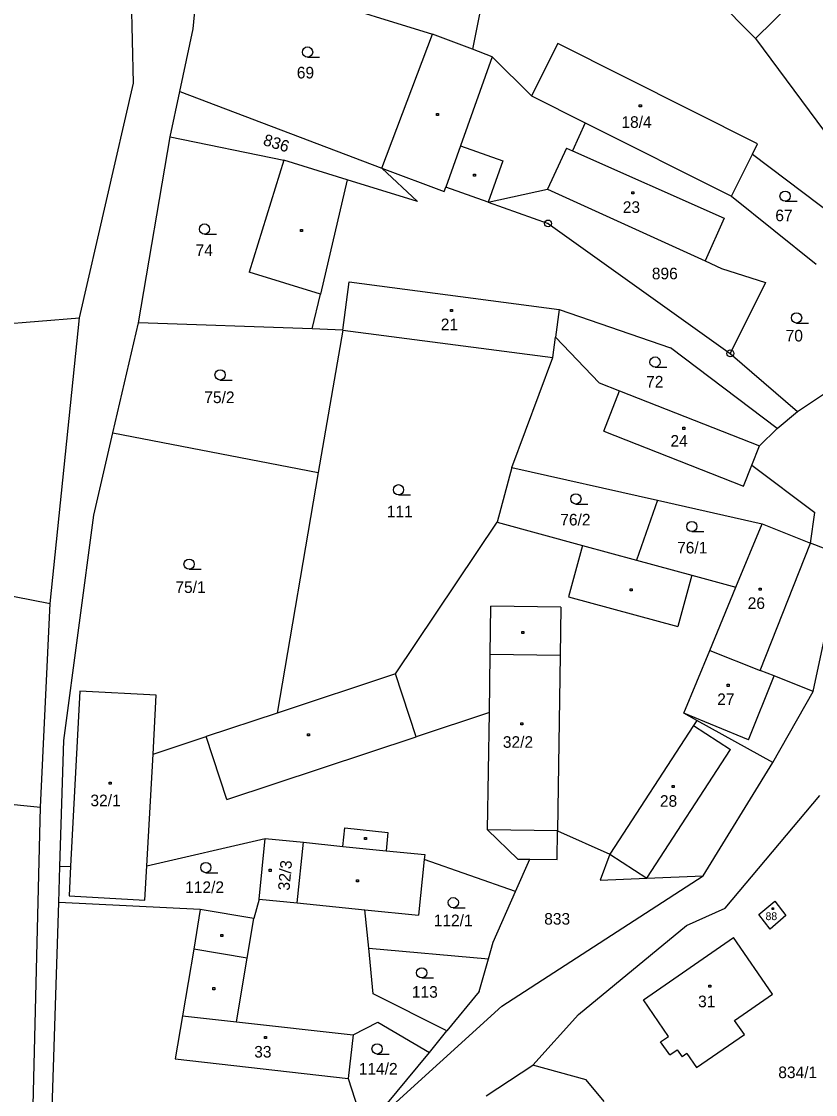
# Model space of a CAD drawing. Extents: x -791032 to -787751, y -1106872 to -1104403.
# Drawn here: x -789576 to -789459.7, y -1105520.6 to -1105363.5 of the extents above; entities that cross this region are included whole.
import ezdxf

# ---------------------------------------------------------------- set-up
doc = ezdxf.new("R2010")
doc.units = 0
for name, color, linetype in [('Vrstva 1', 7, 'Continuous'), ('Vrstva 14', 7, 'Continuous'), ('Vrstva 15', 7, 'Continuous'), ('Vrstva 2', 7, 'Continuous'), ('Vrstva 23', 7, 'Continuous'), ('Vrstva 25', 7, 'Continuous'), ('Vrstva 28', 7, 'Continuous')]:
    doc.layers.add(name, color=color, linetype=linetype)

msp = doc.modelspace()

# ---------------------------------------------------------------- linework, layer by layer
at = {"layer": 'Vrstva 1'}
for p, q in [((-789468.52, -1105366.04), (-789491.02, -1105343.38)), ((-789550.83, -1105364.62), (-789549.93, -1105354.86)), ((-789549.93, -1105354.86), (-789515.79, -1105365.39)), ((-789559.57, -1105372.57), (-789559.95, -1105356.13)), ((-789508.16, -1105358.69), (-789509.94, -1105367.61)), ((-789468.52, -1105366.04), (-789463.32, -1105360.91)), ((-789552.79, -1105373.8), (-789550.83, -1105364.62)), ((-789523.22, -1105385), (-789515.79, -1105365.39)), ((-789509.94, -1105367.61), (-789515.79, -1105365.39)), ((-789497.46, -1105366.76), (-789501.32, -1105374.44)), ((-789468.22, -1105381.48), (-789497.46, -1105366.76)), ((-789468.52, -1105366.04), (-789452.74, -1105387.39)), ((-789507.08, -1105368.73), (-789509.94, -1105367.61)), ((-789507.08, -1105368.73), (-789501.32, -1105374.44)), ((-789567.47, -1105406.94), (-789559.57, -1105372.57)), ((-789554.21, -1105380.44), (-789552.79, -1105373.8)), ((-789552.79, -1105373.8), (-789523.22, -1105385)), ((-789501.32, -1105374.44), (-789493.46, -1105378.39)), ((-789493.46, -1105378.39), (-789495.3, -1105382.5)), ((-789493.46, -1105378.39), (-789472.06, -1105389.13)), ((-789558.84, -1105407.68), (-789554.21, -1105380.44)), ((-789554.21, -1105380.44), (-789537.56, -1105383.85)), ((-789468.96, -1105382.96), (-789468.22, -1105381.48)), ((-789495.3, -1105382.5), (-789473.12, -1105392.36)), ((-789472.06, -1105389.13), (-789468.96, -1105382.96)), ((-789468.96, -1105382.96), (-789456.6, -1105392.29)), ((-789537.56, -1105383.85), (-789542.63, -1105400.22)), ((-789528.28, -1105386.72), (-789537.56, -1105383.85)), ((-789523.22, -1105385), (-789514.09, -1105388.46)), ((-789523.22, -1105385), (-789517.97, -1105389.92)), ((-789517.97, -1105389.92), (-789528.28, -1105386.72)), ((-789514.09, -1105388.46), (-789513.85, -1105387.78)), ((-789507.64, -1105389.99), (-789513.85, -1105387.78)), ((-789507.64, -1105389.99), (-789498.95, -1105388.1)), ((-789498.95, -1105388.1), (-789475.9, -1105398.6)), ((-789472.06, -1105389.13), (-789459.64, -1105399.07)), ((-789507.64, -1105389.99), (-789498.89, -1105393.11)), ((-789473.12, -1105392.36), (-789475.9, -1105398.6)), ((-789498.89, -1105393.11), (-789472.21, -1105412.13)), ((-789475.9, -1105398.6), (-789473.49, -1105399.7)), ((-789532.2, -1105403.45), (-789542.63, -1105400.22)), ((-789473.49, -1105399.7), (-789467.07, -1105401.75)), ((-789467.07, -1105401.75), (-789472.21, -1105412.13)), ((-789533.4, -1105408.56), (-789532.2, -1105403.45)), ((-789497.27, -1105405.7), (-789497.8, -1105409.76)), ((-789497.27, -1105405.7), (-789480.95, -1105411.34)), ((-789634.19, -1105412.22), (-789567.47, -1105406.94)), ((-789571.77, -1105448.75), (-789567.47, -1105406.94)), ((-789562.57, -1105423.75), (-789558.84, -1105407.68)), ((-789533.4, -1105408.56), (-789558.84, -1105407.68)), ((-789528.93, -1105408.71), (-789533.4, -1105408.56)), ((-789528.93, -1105408.71), (-789532.51, -1105429.57)), ((-789528.93, -1105408.71), (-789498.19, -1105412.74)), ((-789498.19, -1105412.74), (-789497.8, -1105409.76)), ((-789497.8, -1105409.76), (-789491.39, -1105416.43)), ((-789465.35, -1105423.12), (-789480.95, -1105411.34)), ((-789504.17, -1105428.82), (-789498.19, -1105412.74)), ((-789472.21, -1105412.13), (-789462.38, -1105420.65)), ((-789491.39, -1105416.43), (-789488.41, -1105417.6)), ((-789488.41, -1105417.6), (-789467.94, -1105425.65)), ((-789462.38, -1105420.65), (-789456.67, -1105416.81)), ((-789465.35, -1105423.12), (-789462.38, -1105420.65)), ((-789565.38, -1105435.83), (-789562.57, -1105423.75)), ((-789562.57, -1105423.75), (-789532.51, -1105429.57)), ((-789467.94, -1105425.65), (-789465.35, -1105423.12)), ((-789469.05, -1105428.48), (-789467.94, -1105425.65)), ((-789469.05, -1105428.48), (-789459.84, -1105435.43)), ((-789532.51, -1105429.57), (-789538.55, -1105464.78)), ((-789504.17, -1105428.82), (-789506.34, -1105436.85)), ((-789504.17, -1105428.82), (-789482.88, -1105433.62)), ((-789482.88, -1105433.62), (-789485.95, -1105442.38)), ((-789482.88, -1105433.62), (-789467.57, -1105437.07)), ((-789636.17, -1105436.07), (-789571.77, -1105448.75)), ((-789569.73, -1105468.8), (-789565.38, -1105435.83)), ((-789460.46, -1105439.89), (-789459.84, -1105435.43)), ((-789521.23, -1105459.03), (-789506.34, -1105436.85)), ((-789506.34, -1105436.85), (-789493.84, -1105440.24)), ((-789471.39, -1105446.33), (-789467.57, -1105437.07)), ((-789467.57, -1105437.07), (-789460.46, -1105439.89)), ((-789493.84, -1105440.24), (-789485.95, -1105442.38)), ((-789455.86, -1105441.72), (-789460.46, -1105439.89)), ((-789485.95, -1105442.38), (-789477.83, -1105444.58)), ((-789460.1, -1105461.61), (-789455.86, -1105441.72)), ((-789477.83, -1105444.58), (-789471.39, -1105446.33)), ((-789475.22, -1105455.61), (-789471.39, -1105446.33)), ((-789573.18, -1105478.57), (-789571.77, -1105448.75)), ((-789479.01, -1105464.81), (-789475.22, -1105455.61)), ((-789475.22, -1105455.61), (-789467.85, -1105458.53)), ((-789465.81, -1105459.34), (-789467.85, -1105458.53)), ((-789521.23, -1105459.03), (-789538.55, -1105464.78)), ((-789518.17, -1105468.24), (-789521.23, -1105459.03)), ((-789460.1, -1105461.61), (-789465.81, -1105459.34)), ((-789567.4, -1105461.58), (-789568.76, -1105487.18)), ((-789556.22, -1105462.17), (-789567.4, -1105461.58)), ((-789466, -1105472.04), (-789460.1, -1105461.61)), ((-789556.7, -1105470.81), (-789556.22, -1105462.17)), ((-789538.55, -1105464.78), (-789548.94, -1105468.23)), ((-789507.48, -1105464.69), (-789518.17, -1105468.24)), ((-789507.73, -1105481.87), (-789507.48, -1105464.69)), ((-789477.13, -1105465.85), (-789479.01, -1105464.81)), ((-789477.13, -1105465.85), (-789477.62, -1105466.6)), ((-789466, -1105472.04), (-789477.13, -1105465.85)), ((-789477.62, -1105466.6), (-789489.85, -1105485.42)), ((-789570.33, -1105487.22), (-789569.73, -1105468.8)), ((-789556.7, -1105470.81), (-789548.94, -1105468.23)), ((-789476.2, -1105488.61), (-789466, -1105472.04)), ((-789599.62, -1105475.92), (-789573.18, -1105478.57)), ((-789472.97, -1105493.34), (-789459.11, -1105476.85)), ((-789574.71, -1105542.67), (-789573.18, -1105478.57)), ((-789507.73, -1105481.87), (-789503.33, -1105486.15)), ((-789497.56, -1105486.23), (-789497.5, -1105482.02)), ((-789497.5, -1105482.02), (-789489.85, -1105485.42)), ((-789557.63, -1105487.16), (-789540.29, -1105483.13)), ((-789541.19, -1105492), (-789540.29, -1105483.13)), ((-789540.29, -1105483.13), (-789534.7, -1105483.7)), ((-789535.6, -1105492.57), (-789534.7, -1105483.7)), ((-789517, -1105486.23), (-789517.83, -1105494.38)), ((-789503.64, -1105490.91), (-789517, -1105486.23)), ((-789503.64, -1105490.91), (-789501.54, -1105486.17)), ((-789503.33, -1105486.15), (-789501.54, -1105486.17)), ((-789501.54, -1105486.17), (-789497.56, -1105486.23)), ((-789489.85, -1105485.42), (-789491.24, -1105489.24)), ((-789570.5, -1105492.53), (-789570.33, -1105487.22)), ((-789570.33, -1105487.22), (-789568.76, -1105487.18)), ((-789568.76, -1105487.18), (-789568.99, -1105491.52)), ((-789557.91, -1105492.15), (-789557.63, -1105487.16)), ((-789505.66, -1105507.7), (-789476.2, -1105488.61)), ((-789491.24, -1105489.24), (-789484.42, -1105488.95)), ((-789484.42, -1105488.95), (-789476.2, -1105488.61)), ((-789568.99, -1105491.52), (-789557.91, -1105492.15)), ((-789506.92, -1105498.3), (-789503.64, -1105490.91)), ((-789571.66, -1105528.32), (-789570.5, -1105492.53)), ((-789549.78, -1105493.55), (-789570.5, -1105492.53)), ((-789541.19, -1105492), (-789541.93, -1105494.87)), ((-789541.19, -1105492), (-789535.6, -1105492.57)), ((-789535.6, -1105492.57), (-789525.68, -1105493.58)), ((-789468.05, -1105494.28), (-789465.71, -1105492.33)), ((-789465.71, -1105492.33), (-789464.08, -1105494.42)), ((-789549.78, -1105493.55), (-789550.75, -1105499.32)), ((-789541.93, -1105494.87), (-789549.78, -1105493.55)), ((-789525.14, -1105499.19), (-789525.68, -1105493.58)), ((-789525.68, -1105493.58), (-789517.83, -1105494.38)), ((-789478.61, -1105495.86), (-789472.97, -1105493.34)), ((-789466.39, -1105496.39), (-789468.05, -1105494.28)), ((-789464.08, -1105494.42), (-789466.39, -1105496.39)), ((-789494.41, -1105508.91), (-789478.61, -1105495.86)), ((-789484.94, -1105506.75), (-789471.73, -1105497.63)), ((-789466.02, -1105505.94), (-789471.73, -1105497.63)), ((-789550.75, -1105499.32), (-789552.4, -1105509.09)), ((-789524.5, -1105505.87), (-789525.14, -1105499.19)), ((-789525.14, -1105499.19), (-789507.61, -1105500.74)), ((-789507.61, -1105500.74), (-789506.92, -1105498.3)), ((-789508.97, -1105505.52), (-789507.61, -1105500.74)), ((-789508.97, -1105505.52), (-789513.68, -1105511.31)), ((-789513.68, -1105511.31), (-789524.5, -1105505.87)), ((-789481.26, -1105512.12), (-789484.94, -1105506.75)), ((-789471.59, -1105509.79), (-789466.02, -1105505.94)), ((-789525.71, -1105525.9), (-789505.66, -1105507.7)), ((-789552.4, -1105509.09), (-789553.46, -1105515.4)), ((-789527.41, -1105511.9), (-789523.79, -1105510.03)), ((-789523.79, -1105510.03), (-789516.26, -1105514.48)), ((-789501.1, -1105516.33), (-789494.41, -1105508.91)), ((-789470.16, -1105511.83), (-789471.59, -1105509.79)), ((-789527.41, -1105511.9), (-789528.12, -1105518.25)), ((-789516.26, -1105514.48), (-789513.68, -1105511.31)), ((-789477.14, -1105516.68), (-789470.16, -1105511.83)), ((-789482.43, -1105512.92), (-789481.26, -1105512.12)), ((-789481.06, -1105514.82), (-789482.43, -1105512.92)), ((-789525.71, -1105525.9), (-789516.26, -1105514.48)), ((-789481.06, -1105514.82), (-789479.99, -1105514.07)), ((-789479.99, -1105514.07), (-789479.25, -1105515.08)), ((-789478.56, -1105514.61), (-789479.25, -1105515.08)), ((-789478.56, -1105514.61), (-789477.14, -1105516.68)), ((-789553.46, -1105515.4), (-789528.12, -1105518.25)), ((-789507.93, -1105520.8), (-789501.1, -1105516.33)), ((-789493.29, -1105518.49), (-789501.1, -1105516.33)), ((-789528.12, -1105518.25), (-789525.71, -1105525.9)), ((-789490.67, -1105521.65), (-789493.29, -1105518.49))]:
    msp.add_line(p, q, dxfattribs=at)
at = {"layer": 'Vrstva 2'}
for p, q in [((-789507.08, -1105368.73), (-789511.71, -1105381.76)), ((-789511.71, -1105381.76), (-789513.85, -1105387.78)), ((-789511.71, -1105381.76), (-789505.5, -1105383.97)), ((-789496.21, -1105382.09), (-789498.95, -1105388.1)), ((-789496.21, -1105382.09), (-789495.3, -1105382.5)), ((-789505.5, -1105383.97), (-789507.64, -1105389.99)), ((-789528.28, -1105386.72), (-789532.2, -1105403.45)), ((-789528.93, -1105408.71), (-789528.01, -1105401.67)), ((-789528.01, -1105401.67), (-789497.27, -1105405.7)), ((-789490.73, -1105423.5), (-789488.41, -1105417.6)), ((-789490.73, -1105423.5), (-789470.26, -1105431.55)), ((-789470.26, -1105431.55), (-789469.05, -1105428.48)), ((-789493.84, -1105440.24), (-789495.89, -1105447.79)), ((-789467.85, -1105458.53), (-789460.46, -1105439.89)), ((-789477.83, -1105444.58), (-789479.88, -1105452.13)), ((-789507.36, -1105456.22), (-789507.26, -1105449.14)), ((-789497.03, -1105449.29), (-789507.26, -1105449.14)), ((-789495.89, -1105447.79), (-789479.88, -1105452.13)), ((-789497.03, -1105449.29), (-789497.13, -1105456.37)), ((-789507.48, -1105464.69), (-789507.36, -1105456.22)), ((-789497.13, -1105456.37), (-789507.36, -1105456.22)), ((-789497.13, -1105456.37), (-789497.5, -1105482.02)), ((-789469.53, -1105468.72), (-789465.81, -1105459.34)), ((-789469.53, -1105468.72), (-789479.01, -1105464.81)), ((-789477.62, -1105466.6), (-789472.19, -1105470.13)), ((-789545.88, -1105477.44), (-789548.94, -1105468.23)), ((-789545.88, -1105477.44), (-789518.17, -1105468.24)), ((-789557.63, -1105487.16), (-789556.7, -1105470.81)), ((-789484.42, -1105488.95), (-789472.19, -1105470.13)), ((-789528.9, -1105484.29), (-789528.62, -1105481.6)), ((-789528.62, -1105481.6), (-789522.33, -1105482.24)), ((-789497.5, -1105482.02), (-789507.73, -1105481.87)), ((-789534.7, -1105483.7), (-789528.9, -1105484.29)), ((-789522.33, -1105482.24), (-789522.6, -1105484.93)), ((-789528.9, -1105484.29), (-789522.6, -1105484.93)), ((-789522.6, -1105484.93), (-789516.93, -1105485.5)), ((-789516.93, -1105485.5), (-789517, -1105486.23)), ((-789489.85, -1105485.42), (-789484.42, -1105488.95)), ((-789542.9, -1105500.65), (-789541.93, -1105494.87)), ((-789542.9, -1105500.65), (-789550.75, -1105499.32)), ((-789544.47, -1105509.98), (-789542.9, -1105500.65)), ((-789552.4, -1105509.09), (-789544.47, -1105509.98)), ((-789544.47, -1105509.98), (-789527.41, -1105511.9))]:
    msp.add_line(p, q, dxfattribs=at)
at = {"layer": 'Vrstva 23'}
for p, q in [((-789534.08, -1105368.77), (-789532.33, -1105368.77)), ((-789464.2, -1105389.87), (-789462.45, -1105389.87)), ((-789549.17, -1105394.68), (-789547.42, -1105394.68)), ((-789462.51, -1105407.69), (-789460.76, -1105407.69)), ((-789483.23, -1105414.15), (-789481.48, -1105414.15)), ((-789546.88, -1105416.03), (-789545.13, -1105416.03)), ((-789520.77, -1105432.84), (-789519.02, -1105432.84)), ((-789494.81, -1105434.18), (-789493.06, -1105434.18)), ((-789477.84, -1105438.22), (-789476.09, -1105438.22)), ((-789551.42, -1105443.73), (-789549.67, -1105443.73)), ((-789548.97, -1105488.15), (-789547.22, -1105488.15)), ((-789512.75, -1105493.28), (-789511, -1105493.28)), ((-789517.38, -1105503.55), (-789515.63, -1105503.55)), ((-789523.91, -1105514.69), (-789522.16, -1105514.69))]:
    msp.add_line(p, q, dxfattribs=at)
for centre in [(-789534.08, -1105368.02), (-789464.2, -1105389.12), (-789549.17, -1105393.93), (-789462.51, -1105406.94), (-789483.23, -1105413.4), (-789546.88, -1105415.28), (-789520.77, -1105432.09), (-789494.81, -1105433.43), (-789477.84, -1105437.47), (-789551.42, -1105442.98), (-789548.97, -1105487.4), (-789512.75, -1105492.53), (-789517.38, -1105502.8), (-789523.91, -1105513.94)]:
    msp.add_circle(centre, 0.75, dxfattribs=at)
at = {"layer": 'Vrstva 25'}
for p, q in [((-789485.53, -1105375.73), (-789485.23, -1105375.73)), ((-789485.53, -1105376.03), (-789485.53, -1105375.73)), ((-789485.23, -1105376.03), (-789485.53, -1105376.03)), ((-789485.23, -1105375.73), (-789485.23, -1105376.03)), ((-789515.22, -1105377), (-789514.92, -1105377)), ((-789515.22, -1105377.3), (-789515.22, -1105377)), ((-789514.92, -1105377.3), (-789515.22, -1105377.3)), ((-789514.92, -1105377), (-789514.92, -1105377.3)), ((-789509.8, -1105385.88), (-789509.5, -1105385.88)), ((-789509.8, -1105386.18), (-789509.8, -1105385.88)), ((-789509.5, -1105386.18), (-789509.8, -1105386.18)), ((-789509.5, -1105385.88), (-789509.5, -1105386.18)), ((-789486.64, -1105388.5), (-789486.34, -1105388.5)), ((-789486.64, -1105388.8), (-789486.64, -1105388.5)), ((-789486.34, -1105388.8), (-789486.64, -1105388.8)), ((-789486.34, -1105388.5), (-789486.34, -1105388.8)), ((-789535.12, -1105393.99), (-789534.82, -1105393.99)), ((-789535.12, -1105394.29), (-789535.12, -1105393.99)), ((-789534.82, -1105393.99), (-789534.82, -1105394.29)), ((-789534.82, -1105394.29), (-789535.12, -1105394.29)), ((-789513.18, -1105405.71), (-789512.88, -1105405.71)), ((-789513.18, -1105406.01), (-789513.18, -1105405.71)), ((-789512.88, -1105406.01), (-789513.18, -1105406.01)), ((-789512.88, -1105405.71), (-789512.88, -1105406.01)), ((-789479.17, -1105422.95), (-789478.87, -1105422.95)), ((-789479.17, -1105423.25), (-789479.17, -1105422.95)), ((-789478.87, -1105423.25), (-789479.17, -1105423.25)), ((-789478.87, -1105422.95), (-789478.87, -1105423.25)), ((-789486.89, -1105446.58), (-789486.59, -1105446.58)), ((-789486.89, -1105446.88), (-789486.89, -1105446.58)), ((-789486.59, -1105446.88), (-789486.89, -1105446.88)), ((-789486.59, -1105446.58), (-789486.59, -1105446.88)), ((-789467.99, -1105446.5), (-789467.69, -1105446.5)), ((-789467.99, -1105446.8), (-789467.99, -1105446.5)), ((-789467.69, -1105446.8), (-789467.99, -1105446.8)), ((-789467.69, -1105446.5), (-789467.69, -1105446.8)), ((-789502.71, -1105452.83), (-789502.41, -1105452.83)), ((-789502.71, -1105453.13), (-789502.71, -1105452.83)), ((-789502.41, -1105453.13), (-789502.71, -1105453.13)), ((-789502.41, -1105452.83), (-789502.41, -1105453.13)), ((-789472.67, -1105460.57), (-789472.37, -1105460.57)), ((-789472.67, -1105460.87), (-789472.67, -1105460.57)), ((-789472.37, -1105460.87), (-789472.67, -1105460.87)), ((-789472.37, -1105460.57), (-789472.37, -1105460.87)), ((-789502.87, -1105466.19), (-789502.57, -1105466.19)), ((-789502.87, -1105466.49), (-789502.87, -1105466.19)), ((-789502.57, -1105466.19), (-789502.57, -1105466.49)), ((-789534.08, -1105467.83), (-789533.78, -1105467.83)), ((-789534.08, -1105468.13), (-789534.08, -1105467.83)), ((-789533.78, -1105467.83), (-789533.78, -1105468.13)), ((-789502.57, -1105466.49), (-789502.87, -1105466.49)), ((-789533.78, -1105468.13), (-789534.08, -1105468.13)), ((-789563.11, -1105474.91), (-789562.81, -1105474.91)), ((-789563.11, -1105475.21), (-789563.11, -1105474.91)), ((-789562.81, -1105475.21), (-789563.11, -1105475.21)), ((-789562.81, -1105474.91), (-789562.81, -1105475.21)), ((-789480.72, -1105475.36), (-789480.42, -1105475.36)), ((-789480.72, -1105475.66), (-789480.72, -1105475.36)), ((-789480.42, -1105475.66), (-789480.72, -1105475.66)), ((-789480.42, -1105475.36), (-789480.42, -1105475.66)), ((-789525.77, -1105483), (-789525.47, -1105483)), ((-789525.77, -1105483.3), (-789525.77, -1105483)), ((-789525.47, -1105483.3), (-789525.77, -1105483.3)), ((-789525.47, -1105483), (-789525.47, -1105483.3)), ((-789539.72, -1105487.65), (-789539.42, -1105487.65)), ((-789539.72, -1105487.95), (-789539.72, -1105487.65)), ((-789539.42, -1105487.95), (-789539.72, -1105487.95)), ((-789539.42, -1105487.65), (-789539.42, -1105487.95)), ((-789526.93, -1105489.17), (-789526.63, -1105489.17)), ((-789526.93, -1105489.47), (-789526.93, -1105489.17)), ((-789526.63, -1105489.47), (-789526.93, -1105489.47)), ((-789526.63, -1105489.17), (-789526.63, -1105489.47)), ((-789466.077, -1105493.313), (-789465.876, -1105493.313)), ((-789466.077, -1105493.514), (-789466.077, -1105493.313)), ((-789465.876, -1105493.514), (-789466.077, -1105493.514)), ((-789465.876, -1105493.313), (-789465.876, -1105493.514)), ((-789546.8, -1105497.19), (-789546.5, -1105497.19)), ((-789546.8, -1105497.49), (-789546.8, -1105497.19)), ((-789546.5, -1105497.49), (-789546.8, -1105497.49)), ((-789546.5, -1105497.19), (-789546.5, -1105497.49)), ((-789547.96, -1105504.97), (-789547.66, -1105504.97)), ((-789547.96, -1105505.27), (-789547.96, -1105504.97)), ((-789547.66, -1105505.27), (-789547.96, -1105505.27)), ((-789547.66, -1105504.97), (-789547.66, -1105505.27)), ((-789475.35, -1105504.62), (-789475.05, -1105504.62)), ((-789475.35, -1105504.92), (-789475.35, -1105504.62)), ((-789475.05, -1105504.92), (-789475.35, -1105504.92)), ((-789475.05, -1105504.62), (-789475.05, -1105504.92)), ((-789540.37, -1105512.11), (-789540.07, -1105512.11)), ((-789540.37, -1105512.41), (-789540.37, -1105512.11)), ((-789540.07, -1105512.41), (-789540.37, -1105512.41)), ((-789540.07, -1105512.11), (-789540.07, -1105512.41))]:
    msp.add_line(p, q, dxfattribs=at)
at = {"layer": 'Vrstva 28'}
for centre, radius in [((-789498.89, -1105393.11), 0.5), ((-789498.89, -1105393.11), 0.01), ((-789472.21, -1105412.13), 0.5), ((-789472.21, -1105412.13), 0.01)]:
    msp.add_circle(centre, radius, dxfattribs=at)

# ---------------------------------------------------------------- texts
at = {"layer": 'Vrstva 14'}
for s, p in [('69', (-789535.657, -1105371.89)), ('67', (-789465.623, -1105392.79)), ('74', (-789550.469, -1105397.88)), ('896', (-789483.697, -1105401.29)), ('70', (-789464.113, -1105410.39)), ('72', (-789484.533, -1105417.13)), ('75/2', (-789549.193, -1105419.41)), ('111', (-789522.486, -1105436.12)), ('76/2', (-789497.096, -1105437.32)), ('76/1', (-789480, -1105441.42)), ('75/1', (-789553.426, -1105447.2)), ('112/2', (-789551.996, -1105491.12)), ('112/1', (-789515.619, -1105495.98)), ('833', (-789499.447, -1105495.75)), ('113', (-789518.813, -1105506.45)), ('114/2', (-789526.592, -1105517.7)), ('834/1', (-789465.189, -1105518.22))]:
    msp.add_text(s, height=1.7, dxfattribs=at).set_placement(p)
msp.add_text('836', height=1.7, rotation=342.63981, dxfattribs=at).set_placement((-789540.706, -1105381.598))
at = {"layer": 'Vrstva 15'}
for s, height, p in [('18/4', 1.7, (-789488.149, -1105379.12)), ('23', 1.7, (-789487.947, -1105391.57)), ('21', 1.7, (-789514.59, -1105408.74)), ('24', 1.7, (-789480.972, -1105425.79)), ('26', 1.7, (-789469.667, -1105449.54)), ('27', 1.7, (-789474.133, -1105463.61)), ('32/2', 1.7, (-789505.5, -1105469.87)), ('32/1', 1.7, (-789565.863, -1105478.42)), ('28', 1.7, (-789482.516, -1105478.5)), ('88', 1.14, (-789467.053, -1105495.09)), ('31', 1.7, (-789476.93, -1105507.84)), ('33', 1.7, (-789541.887, -1105515.21))]:
    msp.add_text(s, height=height, dxfattribs=at).set_placement(p)
msp.add_text('32/3', height=1.7, rotation=85.08528, dxfattribs=at).set_placement((-789536.725, -1105490.81))

doc.saveas('drawing.dxf')
